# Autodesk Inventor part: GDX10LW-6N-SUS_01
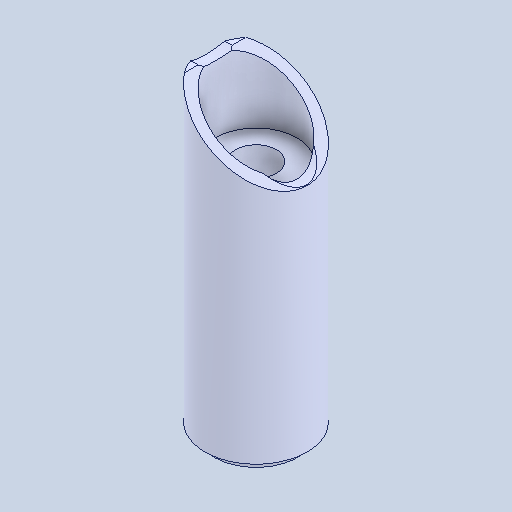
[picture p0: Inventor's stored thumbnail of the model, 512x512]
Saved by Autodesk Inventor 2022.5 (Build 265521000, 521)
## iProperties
Created: 2024-06
Part Number: GDX10LW-6N-SUS_01
Material: 一般
Document SubType Name: Modeling
Designer: ImaoCorp
Density: 1 g/cm^3
Appearance: 既定
Author: ImaoCorp
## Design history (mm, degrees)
feature "GDX10LW-6N-SUS_01"
node "ソリッド1"
